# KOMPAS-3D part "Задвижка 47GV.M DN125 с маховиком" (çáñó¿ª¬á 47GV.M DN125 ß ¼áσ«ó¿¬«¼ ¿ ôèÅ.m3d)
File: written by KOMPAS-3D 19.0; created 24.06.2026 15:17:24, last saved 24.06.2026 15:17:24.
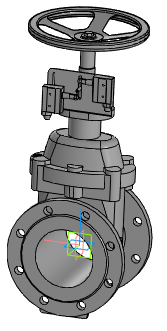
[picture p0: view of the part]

Document properties: Автор: Энергия; Полное имя файла: Z:\3.Личные\sachek\Dendor\3D для проектировщиков\2.7 Тип 47GV.M Задвижка клиновая фланцевая с обрезиненным клином\47GV.M DN125\Задвижка 47GV.M DN125 с маховиком.a3d

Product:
- Part/product: Задвижка 47GV.M DN125 с маховиком
    Масса: 40.0518
    source file: ..\47GV.M DN125\DR.47GVM.125.16.00.00 - Задвижка с обрезиненным клином DN125.spw
  - Component: Задвижка с обрезиненным клином DN125. Сборочный чертеж  | designation DR.47GVM.125.16.00.00СБ  | pos. 0  | Масса: 25.3494; Раздел спецификации: Документация; Форматы листов документа: 2xA3; source file: ..\47GV.M DN125\DR.47GVM.125.16.00.000 СБ - Задвижка с обрезиненным клином DN125.cdw

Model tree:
1. Операция без истории:1

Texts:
  Точка начала. Х
  Точка начала. Y
  Точка начала. Z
